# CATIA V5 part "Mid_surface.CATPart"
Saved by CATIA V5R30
Part number: Part1
Bounding box of the stored display mesh (mm): x -50 to 50, y -40.257 to 69.743, z 0 to 105
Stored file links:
  D:\PROJECTS\CATIA V56R 2020\Resources\Parts File\c17_catia_v6_6r2020_prt\Mid_surface.CATPart
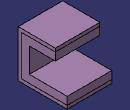
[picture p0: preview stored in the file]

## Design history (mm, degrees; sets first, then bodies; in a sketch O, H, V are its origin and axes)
Body1 (main body)
  Sketch1 on yz-plane, origin (0, 0, 0), H (0, 1, 0), V (0, 0, 1)
    point P1 (-40.2568, 105)
    line L1 (-15.2568, 80) -> (-15.2568, 25)
    line L2 (-40.2568, 0) -> (-40.2568, 105)
    point P3 (-40.2568, 0)
    point P4 (-15.2568, 25)
    line L3 (-15.2568, 25) -> (69.7432, 25)
    line L4 (69.7432, 25) -> (69.7432, 0)
    line L5 (69.7432, 0) -> (-40.2568, 0)
    point P5 (69.7432, 25)
    point P6 (69.7432, 0)
    point P7 (-40.2568, 0)
    reference intersected line E1 through (0, 0) direction (-1, 0) from xy-plane
    reference intersected line E2 through (0, 0) direction (0, 1) from zx-plane
    reference intersected line E4 through (0, 0) direction (0, 1) from zx-plane
    line L6 (-15.2568, 80) -> (43.024, 80)
    line L7 (43.024, 80) -> (43.024, 105)
    line L8 (43.024, 105) -> (-40.2568, 105)
    point P10 (-40.2568, 105)
    distance P4 P5 = 85
    distance L6 L8 = 25
    distance L8 H = 105
    vertical: L1 V, L2 V, L4 V, E2 V, E4 V, L7 V
    horizontal: L3 H, L5 H, E1 H, L6 H, L8 H
    coincidence: P6 H, E1 P3, P1 P10, P3 P7
  Set1
    Extrude1: Element1 Sketch1, Lim1 50, Lim2 50
    MidSurface1: InputSolid Extrude1, FacePairs ({midsurfacefacepair Face1 face of Extrude1 from Sketch1.L3, Face2 face of Extrude1 from Sketch1.L5}; {midsurfacefacepair Face1 face of Extrude1 from Sketch1.L1, Face2 face of Extrude1 from Sketch1.L2}; {midsurfacefacepair Face1 face of Extrude1 from Sketch1.L6, Face2 face of Extrude1 from Sketch1.L8}), OffsetRatio 0.3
